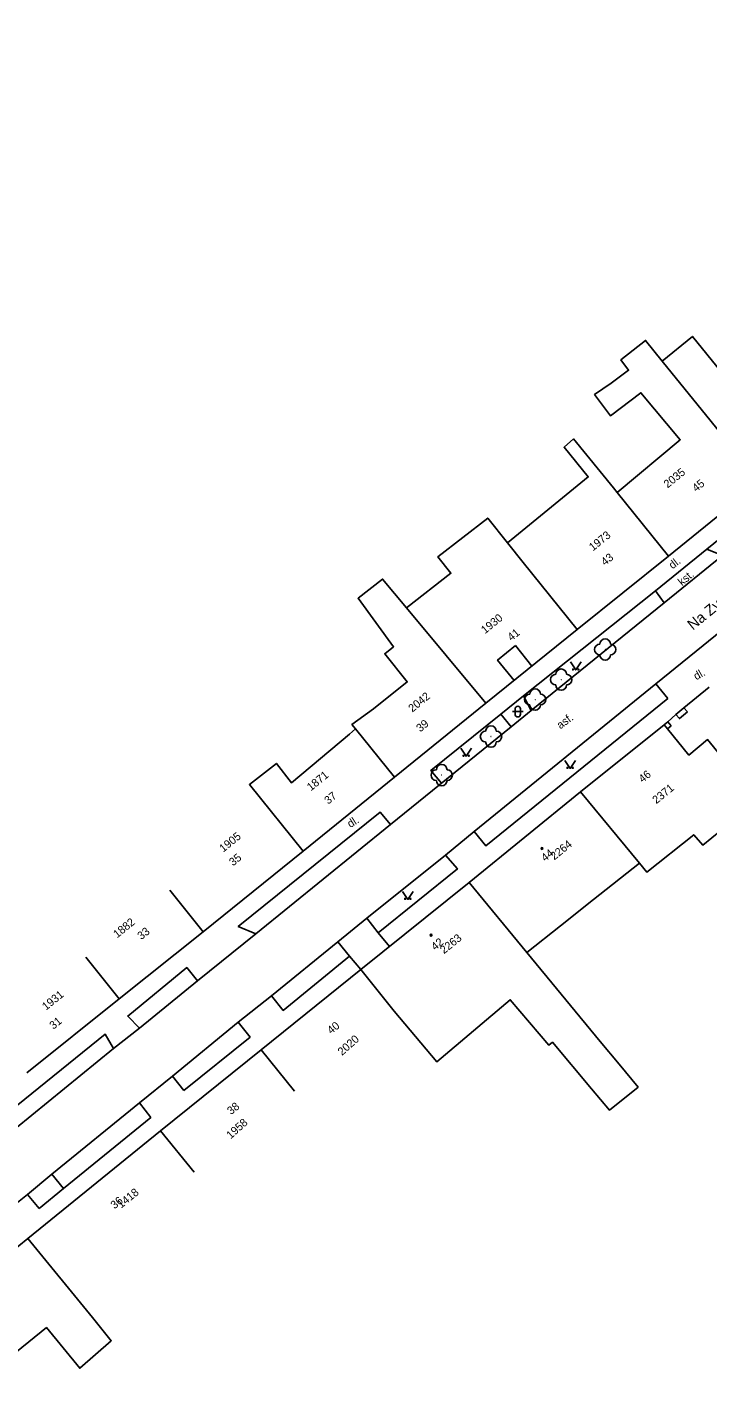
# Model space of a CAD drawing. Extents: x -584400 to -581602, y -1210894 to -1208793.
# Drawn here: x -582245.9 to -582182.1, y -1209584.9 to -1209457.6 of the extents above; entities that cross this region are included whole.
import ezdxf

# ---------------------------------------------------------------- set-up
doc = ezdxf.new("R2010")
doc.units = 0
for name, color, linetype in [('BUDOVY_MĚŘ', 7, 'Continuous'), ('NÁZVY_ULIC_TOK_SMĚR', 7, 'Continuous'), ('POMOC_POPIS', 7, 'Continuous'), ('ROZHRANÍ_PLOCH', 7, 'Continuous'), ('ZELEŇ', 7, 'Continuous'), ('ZN_BUDOV', 7, 'Continuous'), ('ZN_DOPLŇKOVÉ', 7, 'Continuous'), ('ZN_KULTUR', 7, 'Continuous'), ('Č_POPIS_EVID', 7, 'Continuous')]:
    doc.layers.add(name, color=color, linetype=linetype)

msp = doc.modelspace()

# ---------------------------------------------------------------- linework, layer by layer
at = {"layer": 'BUDOVY_MĚŘ'}
for points in [[(-582145.59, -1209454.65), (-582141.65, -1209451.58), (-582132.22, -1209463.66), (-582137.96, -1209468.33), (-582146.47, -1209475.24), (-582155.56, -1209482.65), (-582160.06, -1209486.32), (-582168.59, -1209493.24), (-582177.22, -1209500.22), (-582185.79, -1209507.17), (-582194.36, -1209514.06), (-582202.92, -1209520.97), (-582211.46, -1209527.9), (-582220.04, -1209534.83), (-582229.4, -1209542.38)], [(-582190.61, -1209501.23), (-582184.69, -1209496.27), (-582188.38, -1209491.87), (-582191.22, -1209494.03), (-582192.73, -1209492.04), (-582191.17, -1209490.96), (-582189.54, -1209489.75), (-582190.25, -1209488.79), (-582187.95, -1209486.96), (-582186.4, -1209488.89)], [(-582186.4, -1209488.89), (-582183.55, -1209486.58), (-582179.12, -1209492.05), (-582173.35, -1209487.37)], [(-582186.4, -1209488.89), (-582177.22, -1209500.22)], [(-582200.89, -1209505.93), (-582193.31, -1209499.76), (-582195.58, -1209496.97), (-582194.7, -1209496.19), (-582190.96, -1209500.79), (-582190.61, -1209501.23)], [(-582190.61, -1209501.23), (-582185.79, -1209507.17)], [(-582210.36, -1209512.02), (-582206.19, -1209508.79), (-582207.4, -1209507.23), (-582202.73, -1209503.61), (-582200.89, -1209505.93)], [(-582200.89, -1209505.93), (-582199.43, -1209507.76), (-582194.36, -1209514.06)], [(-582210.36, -1209512.02), (-582212.59, -1209509.33), (-582214.89, -1209511.12), (-582211.56, -1209515.67), (-582212.38, -1209516.33), (-582210.28, -1209518.97), (-582213.45, -1209521.49), (-582215.46, -1209522.97), (-582215.13, -1209523.38)], [(-582202.92, -1209520.97), (-582210.36, -1209512.02)], [(-582220.04, -1209534.83), (-582225.07, -1209528.59), (-582222.53, -1209526.61), (-582221.11, -1209528.43), (-582215.69, -1209523.86), (-582215.13, -1209523.38)], [(-582215.13, -1209523.38), (-582211.46, -1209527.9)], [(-582185.89, -1209523.37), (-582186.2, -1209522.98), (-582194.03, -1209529.28), (-582204.49, -1209537.76), (-582214.64, -1209545.93)], [(-582188.51, -1209535.96), (-582187.83, -1209536.79), (-582183.43, -1209533.29), (-582182.59, -1209534.26), (-582180.04, -1209532.2), (-582179.29, -1209533.1), (-582178.51, -1209533.28), (-582177.9, -1209533.21), (-582177.32, -1209532.92), (-582176.9, -1209532.45), (-582176.64, -1209531.83), (-582176.75, -1209531), (-582182.13, -1209524.38), (-582183.89, -1209525.82), (-582185.89, -1209523.37)], [(-582188.51, -1209535.96), (-582194.03, -1209529.28)], [(-582199.07, -1209544.33), (-582195.91, -1209541.83), (-582192.81, -1209539.37), (-582188.51, -1209535.96)], [(-582199.07, -1209544.33), (-582204.49, -1209537.76)], [(-582232.52, -1209538.48), (-582229.4, -1209542.38)], [(-582229.4, -1209542.38), (-582237.27, -1209548.68)], [(-582211.5, -1209549.82), (-582207.51, -1209554.57), (-582200.62, -1209548.76), (-582197.02, -1209553.01), (-582196.67, -1209552.74), (-582193, -1209557.1), (-582191.31, -1209559.11), (-582188.65, -1209556.94), (-582190.42, -1209554.8), (-582192.2, -1209552.66), (-582199.07, -1209544.33)], [(-582240.4, -1209544.78), (-582237.27, -1209548.68)], [(-582214.64, -1209545.93), (-582223.97, -1209553.45)], [(-582211.5, -1209549.82), (-582214.64, -1209545.93)], [(-582237.27, -1209548.68), (-582245.92, -1209555.62)], [(-582223.97, -1209553.45), (-582233.39, -1209561.05)], [(-582220.83, -1209557.34), (-582223.97, -1209553.45)], [(-582233.39, -1209561.05), (-582245.83, -1209571.13)], [(-582230.24, -1209564.93), (-582233.39, -1209561.05)], [(-582245.83, -1209571.13), (-582255.13, -1209578.68), (-582255.2, -1209578.74)], [(-582239.77, -1209578.55), (-582245.83, -1209571.13)], [(-582239.77, -1209578.55), (-582238.01, -1209580.72), (-582240.97, -1209583.29), (-582244.09, -1209579.48), (-582250.4, -1209584.56), (-582250.16, -1209584.85)]]:
    msp.add_lwpolyline(points, dxfattribs=at)
at = {"layer": 'ROZHRANÍ_PLOCH'}
for points in [[(-582180.73, -1209507.12), (-582182.22, -1209506.53), (-582169.93, -1209496.59), (-582169.12, -1209497.7)], [(-582187.02, -1209510.42), (-582182.22, -1209506.53)], [(-582186.21, -1209511.55), (-582180.73, -1209507.12)], [(-582199.37, -1209520.26), (-582187.02, -1209510.42)], [(-582186.21, -1209511.55), (-582187.02, -1209510.42)], [(-582198.66, -1209521.64), (-582186.21, -1209511.55)], [(-582180.75, -1209514.1), (-582186.98, -1209519.16)], [(-582200.14, -1209515.57), (-582201.81, -1209516.92), (-582200.27, -1209518.83)], [(-582200.14, -1209515.57), (-582198.6, -1209517.48)], [(-582186.98, -1209519.16), (-582204.01, -1209532.99)], [(-582185.87, -1209520.52), (-582186.98, -1209519.16)], [(-582185.87, -1209520.52), (-582202.9, -1209534.34), (-582204.01, -1209532.99)], [(-582199.37, -1209520.26), (-582201.52, -1209521.99)], [(-582199.37, -1209520.26), (-582198.66, -1209521.64)], [(-582207.08, -1209528.47), (-582208.06, -1209527.26), (-582201.52, -1209521.99)], [(-582201.52, -1209521.99), (-582200.55, -1209523.19)], [(-582200.55, -1209523.19), (-582198.66, -1209521.64)], [(-582211.85, -1209532.34), (-582200.55, -1209523.19)], [(-582224.47, -1209542.59), (-582226.12, -1209541.89), (-582212.81, -1209531.19), (-582211.85, -1209532.34)], [(-582224.47, -1209542.59), (-582211.85, -1209532.34)], [(-582204.01, -1209532.99), (-582206.7, -1209535.2)], [(-582206.7, -1209535.2), (-582214.07, -1209541.11)], [(-582206.7, -1209535.2), (-582205.58, -1209536.49), (-582213, -1209542.47)], [(-582214.07, -1209541.11), (-582216.77, -1209543.32)], [(-582213, -1209542.47), (-582214.07, -1209541.11)], [(-582229.94, -1209546.97), (-582224.47, -1209542.59)], [(-582211.95, -1209543.77), (-582213, -1209542.47)], [(-582216.77, -1209543.32), (-582223, -1209548.4)], [(-582216.77, -1209543.32), (-582215.68, -1209544.66)], [(-582215.68, -1209544.66), (-582221.89, -1209549.75), (-582223, -1209548.4)], [(-582215.68, -1209544.66), (-582214.64, -1209545.93)], [(-582235.36, -1209551.41), (-582236.47, -1209550.28), (-582230.94, -1209545.74), (-582229.94, -1209546.97)], [(-582235.36, -1209551.41), (-582229.94, -1209546.97)], [(-582223, -1209548.4), (-582226.13, -1209550.87)], [(-582250.08, -1209563.32), (-582251.06, -1209562.03), (-582238.6, -1209551.97), (-582237.79, -1209553.34)], [(-582237.79, -1209553.34), (-582235.36, -1209551.41)], [(-582226.13, -1209550.87), (-582232.29, -1209555.92)], [(-582231.2, -1209557.27), (-582225.01, -1209552.26), (-582226.13, -1209550.87)], [(-582250.08, -1209563.32), (-582237.79, -1209553.34)], [(-582232.29, -1209555.92), (-582235.38, -1209558.42)], [(-582231.2, -1209557.27), (-582232.29, -1209555.92)], [(-582235.38, -1209558.42), (-582243.58, -1209565.11)], [(-582235.38, -1209558.42), (-582234.31, -1209559.78), (-582242.49, -1209566.45)], [(-582243.58, -1209565.11), (-582245.87, -1209567)], [(-582242.49, -1209566.45), (-582243.58, -1209565.11)], [(-582245.87, -1209567), (-582248.06, -1209568.76)], [(-582244.78, -1209568.31), (-582245.87, -1209567)], [(-582242.49, -1209566.45), (-582244.78, -1209568.31)]]:
    msp.add_lwpolyline(points, dxfattribs=at)
at = {"layer": 'ZELEŇ'}
for centre in [(-582191.73, -1209515.93), (-582195.85, -1209518.75), (-582198.29, -1209520.62), (-582202.43, -1209524.09), (-582207.05, -1209527.7)]:
    msp.add_circle(centre, 0.0005, dxfattribs=at)
for centre, start, end in [((-582191.73, -1209515.43), 0, 180), ((-582192.23, -1209515.93), 90, 270), ((-582191.23, -1209515.93), 270, 90), ((-582191.73, -1209516.43), 180, 360), ((-582196.35, -1209518.75), 90, 270), ((-582195.85, -1209518.25), 0, 180), ((-582195.35, -1209518.75), 270, 90), ((-582198.79, -1209520.62), 90, 270), ((-582198.29, -1209520.12), 0, 180), ((-582197.79, -1209520.62), 270, 90), ((-582195.85, -1209519.25), 180, 360), ((-582198.29, -1209521.12), 180, 360), ((-582202.93, -1209524.09), 90, 270), ((-582202.43, -1209523.59), 0, 180), ((-582201.93, -1209524.09), 270, 90), ((-582202.43, -1209524.59), 180, 360), ((-582207.55, -1209527.7), 90, 270), ((-582207.05, -1209527.2), 0, 180), ((-582206.55, -1209527.7), 270, 90), ((-582207.05, -1209528.2), 180, 360)]:
    msp.add_arc(centre, 0.5, start, end, dxfattribs=at)
at = {"layer": 'ZN_BUDOV'}
for centre in [(-582197.65, -1209534.58), (-582208.05, -1209542.7)]:
    msp.add_circle(centre, 0.0875, dxfattribs=at)
at = {"layer": 'ZN_DOPLŇKOVÉ'}
for points in [[(-582182, -1209519.47), (-582184.36, -1209521.4)], [(-582185.1, -1209522.03), (-582184.36, -1209521.4), (-582184.03, -1209521.78)], [(-582186.2, -1209522.98), (-582185.85, -1209522.7), (-582185.54, -1209523.09)], [(-582185.1, -1209522.03), (-582185.85, -1209522.7)], [(-582185.1, -1209522.03), (-582184.77, -1209522.41), (-582184.03, -1209521.78)], [(-582185.89, -1209523.37), (-582185.54, -1209523.09)]]:
    msp.add_lwpolyline(points, dxfattribs=at)
at = {"layer": 'ZN_KULTUR'}
for p, q in [((-582200.42, -1209521.75), (-582199.42, -1209521.75)), ((-582200.17, -1209522), (-582200.17, -1209521.5)), ((-582199.67, -1209522), (-582199.67, -1209521.5))]:
    msp.add_line(p, q, dxfattribs=at)
for points in [[(-582194.99, -1209517.1), (-582194.49, -1209517.85), (-582193.99, -1209517.1)], [(-582205.26, -1209525.19), (-582204.76, -1209525.94), (-582204.26, -1209525.19)], [(-582195.51, -1209526.32), (-582195.01, -1209527.07), (-582194.51, -1209526.32)], [(-582210.72, -1209538.6), (-582210.22, -1209539.35), (-582209.72, -1209538.6)]]:
    msp.add_lwpolyline(points, dxfattribs=at)
for centre in [(-582194.74, -1209517.8), (-582194.24, -1209517.8), (-582205.01, -1209525.89), (-582204.51, -1209525.89), (-582195.26, -1209527.02), (-582194.76, -1209527.02), (-582210.47, -1209539.3), (-582209.97, -1209539.3)]:
    msp.add_circle(centre, 0.05, dxfattribs=at)
for centre, start, end in [((-582199.92, -1209521.5), 0, 180), ((-582199.92, -1209522), 180, 360)]:
    msp.add_arc(centre, 0.25, start, end, dxfattribs=at)

# ---------------------------------------------------------------- texts
at = {"layer": 'NÁZVY_ULIC_TOK_SMĚR'}
msp.add_text('Na Zvolenci', height=1, rotation=39.1617, dxfattribs=at).set_placement((-582183.52, -1209514.16))
at = {"layer": 'POMOC_POPIS'}
for s, rotation, p in [('dl.', 37.6139, (-582185.42, -1209508.43)), ('kst.', 39.9428, (-582184.53, -1209510)), ('dl.', 29.8234, (-582183.19, -1209518.83)), ('asf.', 36.486, (-582195.93, -1209523.42)), ('dl.', 32.6192, (-582215.61, -1209532.67))]:
    msp.add_text(s, height=0.75, rotation=rotation, dxfattribs=at).set_placement(p)
at = {"layer": 'Č_POPIS_EVID'}
for s, rotation, p in [('2035', 38.9929, (-582185.88, -1209500.84)), ('45', 39.0839, (-582183.2, -1209501.2)), ('1973', 38.7989, (-582192.88, -1209506.74)), ('43', 38.8108, (-582191.75, -1209508.12)), ('1930', 38.9929, (-582202.99, -1209514.5)), ('41', 38.8769, (-582200.52, -1209515.18)), ('2042', 39.087, (-582209.8, -1209521.85)), ('39', 39.087, (-582209.06, -1209523.71)), ('1871', 38.9929, (-582219.31, -1209529.23)), ('46', 38.8229, (-582188.23, -1209528.46)), ('2371', 38.9929, (-582186.94, -1209530.44)), ('37', 38.8975, (-582217.68, -1209530.48)), ('1905', 38.9159, (-582227.52, -1209534.97)), ('2264', 39.0464, (-582196.5, -1209535.71)), ('35', 38.9159, (-582226.6, -1209536.26)), ('44', 39.0464, (-582197.36, -1209535.85)), ('1882', 38.9418, (-582237.46, -1209543.01)), ('33', 38.6838, (-582235.2, -1209543.18)), ('42', 38.8254, (-582207.67, -1209544.18)), ('2263', 38.8254, (-582206.84, -1209544.5)), ('1931', 38.7542, (-582244.13, -1209549.79)), ('31', 38.7542, (-582243.44, -1209551.58)), ('40', 38.8763, (-582217.41, -1209552.02)), ('2020', 41.5268, (-582216.39, -1209554.03)), ('38', 38.875, (-582226.79, -1209559.58)), ('1958', 41.5268, (-582226.83, -1209561.85)), ('36', 39.0125, (-582237.71, -1209568.41)), ('1418', 39.0125, (-582237.09, -1209568.34))]:
    msp.add_text(s, height=0.75, rotation=rotation, dxfattribs=at).set_placement(p)

doc.saveas('drawing.dxf')
